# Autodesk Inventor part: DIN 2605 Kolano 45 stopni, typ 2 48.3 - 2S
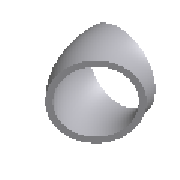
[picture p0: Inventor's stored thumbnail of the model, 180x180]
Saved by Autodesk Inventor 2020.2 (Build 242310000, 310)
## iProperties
Manager: www.cadconsulting.pl
Company: Fabian Stasiak CAD Consulting
IsCustomPart: 0
Created: 2014-02
Part Number: DIN 2605 Kolano 45 stopni, typ 2 48.3 - 2S
Material: Stal
Description: Kolano
Document SubType Name: Modeling
Standard: DIN 2605
Designer: F.Stasiak
Standards Organization: DIN
Language: pl-PL
Size Designation: 48.3 - 2S
Categories: <MemberInstance><Categories><Category DisplayName="Rury cienko- i grubościenne" InternalName="4347fa0f-2144-441d-94cd-e3e15c92b736" Mnemonic="TUBEANDPIPE"><Cate
Density: 1 g/cm^3
Appearance: Płyta
Catalog Web Link: www.expertbooks.pl
NAME: PIPING: DIN 2605 45 Deg Elbow Type 2
DATA: <meta><inlinegroups number="0" deflen="0"></inlinegroups><connections number="2"></connections><angles><a>2.35619449019234</a></angles></meta>
Author: F.Stasiak
Subject: Zbiór ćwiczeń. Autodesk Inventor 2020. Kurs Professional
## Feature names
1. Sweep1
## Parameters: d0 = 44.3 mm, d1 = 48.3 mm, da = 48.3 mm, e = 16 mm, d2 = 16 mm, d3 = 45 deg, d4 = 16 mm, d5 = 0, s1 = 2 mm, d6 = 0, Size_Designation = 12.345 mm
